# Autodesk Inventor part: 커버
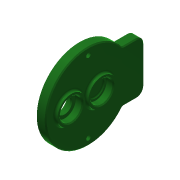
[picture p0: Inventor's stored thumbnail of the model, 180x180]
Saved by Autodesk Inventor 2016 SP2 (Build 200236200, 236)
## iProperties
Created: 2016-02
Part Number: 커버
Material: 알루미늄 6061
Document SubType Name: Modeling
Designer: mduedu
Density: 2.71 g/cm^3
Mass: 157.248 g
Surface Area: 178.476 cm^2
Volume: 58.0252 cm^3
Appearance: 매끄러움 - 짙은 산림 녹색
Author: mduedu
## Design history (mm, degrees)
sketch "스케치1"
  geometry: C1 r 43 at (0, 0); 1 further point
  constraints: 1 centre point, 1 coincident
  dimensions: "d0" = 86 diameter of C1
extrude "돌출1" new body sketch "스케치1" distance "d1" = 9; taper "d2" = 0 deg
sketch "스케치2"
  geometry: C1 r 14 at (0, 11); 1 further point
  constraints: 1 centre point, 1 vertical alignment
  dimensions: "d3" = 28 diameter of C1; "d6" = 11 distance of C1.centre point (0, 0)
extrude "돌출2" join sketch "스케치2" distance "d7" = 3; taper "d8" = 0 deg
sketch "스케치3"
  geometry: C1 r 14 at (0, -20); 1 further point
  constraints: 1 centre point, 1 vertical alignment
  dimensions: "d9" = 28 diameter of C1; "d10" = 20 distance of C1.centre point (0, 0)
extrude "돌출3" join sketch "스케치3" distance "d11" = 3; taper "d12" = 0 deg
hole "구멍1" diameter "d15" = 22; stored, may be unused: countersink angle "d19" = 90 deg, drill point angle "d21" = 0 deg; dims "d13" = 10, "d14" = 10, "d16" = 6, "d17" = 4, "d18" = 2, "d20" = 7
hole "구멍2" diameter "d24" = 18; stored, may be unused: countersink angle "d28" = 90 deg, drill point angle "d30" = 0 deg; dims "d22" = 10, "d23" = 10, "d25" = 6, "d26" = 4, "d27" = 2, "d29" = 1
hole "구멍3" diameter "d33" = 22; stored, may be unused: countersink angle "d37" = 90 deg, drill point angle "d39" = 0 deg; dims "d34" = 6, "d35" = 4, "d36" = 2, "d38" = 7, "d73" = 10, "d74" = 10
sketch "스케치7"
  geometry: L1 (-26, 34.249)-(26, 34.249); L2 (26, 34.249)-(26, 56); L3 (26, 56)-(-26, 56); L4 (-26, 56)-(-26, 34.249); A1 r 43 centre (0, 0) between (-26, 34.249) and (26, 34.249) reference; 1 further point
  constraints: 8 end point, 2 parallel, 2 point on circle, 1 horizontal, 1 perpendicular
  dimensions: "d95" = 52 distance of L2.end L3.end; "d97" = 56 distance from line of L3 point (0, 0)
extrude "돌출5" join sketch "스케치7" stored distance "d98" = 10; taper "d99" = 0 deg
sketch "스케치4"
  geometry: C1 r 14 at (0, -20) reference; C2 r 18 at (0, -20); 1 further point
  constraints: 1 centre point, 1 coincident
  dimensions: "d40" = 36 diameter of C2
extrude "돌출4" join sketch "스케치4" distance "d41" = 4; taper "d42" = 0 deg
hole "구멍4" diameter "d45" = 22; stored, may be unused: countersink angle "d49" = 90 deg, drill point angle "d51" = 0 deg; dims "d43" = 10, "d44" = 10, "d46" = 6, "d47" = 4, "d48" = 2, "d50" = 7
hole "구멍5" diameter "d54" = 15; stored, may be unused: countersink angle "d58" = 90 deg, drill point angle "d60" = 0 deg; dims "d52" = 10, "d53" = 10, "d55" = 6, "d56" = 4, "d57" = 2, "d59" = 7
fillet "모깎기1" dims "d61" = 0.3
fillet "모깎기2" dims "d62" = 2
chamfer "모따기1" distance "d63" = 1; stored, may be unused: second distance "d64" = 2, angle "d65" = 45 deg
fillet "모깎기6" dims "d88" = 2
sketch "스케치5" dims "d67" = 72
  geometry: 4 further points
  constraints: 2 horizontal alignment, 1 coincident, 5 other
  dimensions: "d71" = 360 deg dimension on point (0, 0) point (-36, 0) (derived)
fillet "모깎기4" dims "d75" = 2
sketch "스케치6"
  geometry: 2 further points
hole "구멍6" sketch "스케치6" at (36, 0), (-36, 0) diameter "d76" = 4.5; stored, may be unused: countersink angle "d80" = 90 deg, drill point angle "d82" = 0 deg; dims "d77" = 6, "d78" = 8, "d79" = 4.6, "d81" = 8
fillet "모깎기7" dims "d100" = 8, "d101" = 2
chamfer "모따기2" distance "d90" = 1; stored, may be unused: second distance "d91" = 2, angle "d92" = 45 deg
node "솔리드1"
node "절단 모서리 투영1"
